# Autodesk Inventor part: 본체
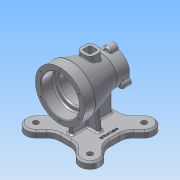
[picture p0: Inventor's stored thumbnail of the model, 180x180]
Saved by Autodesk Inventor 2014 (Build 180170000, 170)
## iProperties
Created: 2018-03
Part Number: 본체
Material: 알루미늄 6061
Document SubType Name: Modeling
Designer: user
Density: 2.71 g/cm^3
Appearance: 알루미늄 - 평지
Mass: 1019.39 g
Surface Area: 857.336 cm^2
Volume: 376.16 cm^3
Author: user
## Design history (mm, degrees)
sketch "스케치1"
  geometry: L1 (0, 0)-(0, 45); L2 (0, 45)-(20, 45); L3 (20, 45)-(77, 27.5); L4 (0, 0)-(100, 0); L5 (77, 27.5)-(100, 27.5); L6 (100, 27.5)-(100, 0)
  constraints: 12 end point, 2 perpendicular, 1 parallel, 1 vertical
  dimensions: "d0" = 20 distance of L1.end L2.end; "d2" = 90 diameter of L2 L4; "d4" = 100 distance between parallel lines of L6 L1; "d5" = 55 diameter of L5.end L4; "d6" = 77 distance from line of L1 L3.end
revolve "회전1" sketch "스케치1" stored, may be unused: angle "d7" = 90 deg
node "작업 평면1"
sketch "스케치2"
  geometry: L1 (55, 0)-(5.503, 49.497); L2 (55, 0)-(-15, 0); L3 (10, -45)-(100, 45); L4 (100, -45)-(10, 45); L5 (64.189, 45)-(45.811, 45); L6 (45.811, -45)-(64.189, -45); L7 (10, 9.189)-(10, -9.189); L8 (100, -9.189)-(100, 9.189); L9 (18.23, 62.225)-(28.134, 52.322); L10 (91.77, 62.225)-(81.866, 52.322); L11 (-7.225, 36.77)-(2.678, 26.866); L12 (2.678, -26.866)-(-7.225, -36.77); L13 (28.134, -52.322)-(18.23, -62.225); L14 (117.225, 36.77)-(107.322, 26.866); L15 (107.322, -26.866)-(117.225, -36.77); L16 (81.866, -52.322)-(91.77, -62.225); C1 r 5 at (5.503, 49.497); C2 r 5 at (5.503, -49.497); C3 r 5 at (104.497, -49.497); C4 r 5 at (104.497, 49.497); A1 r 70 centre (55, 0) between (-15, 0) and (5.503, 49.497); A2 r 18 centre (5.503, 49.497) between (18.23, 62.225) and (-7.225, 36.77); A3 r 18 centre (5.503, -49.497) between (18.23, -62.225) and (-7.225, -36.77); A4 r 18 centre (104.497, -49.497) between (117.225, -36.77) and (91.77, -62.225); A5 r 18 centre (104.497, 49.497) between (91.77, 62.225) and (117.225, 36.77); A6 r 25 centre (45.811, 70) between (28.134, 52.322) and (45.811, 45); A7 r 25 centre (64.189, 70) between (64.189, 45) and (81.866, 52.322); A8 r 25 centre (-15, 9.189) between (10, 9.189) and (2.678, 26.866); A9 r 25 centre (-15, -9.189) between (2.678, -26.866) and (10, -9.189); A10 r 25 centre (45.811, -70) between (45.811, -45) and (28.134, -52.322); A11 r 25 centre (64.189, -70) between (81.866, -52.322) and (64.189, -45); A12 r 25 centre (125, -9.189) between (100, -9.189) and (107.322, -26.866); A13 r 25 centre (125, 9.189) between (107.322, 26.866) and (100, 9.189); 1 further point
  constraints: 32 end point, 28 tangent, 26 point on circle, 17 centre point, 7 equal radius, 5 parallel, 5 perpendicular, 2 coincident, 2 horizontal, 2 midpoint, 1 concentric, 1 horizontal alignment, 18 other
  dimensions: "d9" = 55 distance of L1.start point (0, 0); "d10" = 140 diameter of A1; "d11" = 45 deg angle of L2 L1; "d12" = 10 diameter of C1; "d15" = 360 deg dimension on L1.start C1.centre (derived); "d17" = 36 diameter of A2; "d20" = 360 deg dimension on L1.start A2.centre (derived); "d22" = 90 distance of L4.end L3.end; "d23" = 90 distance of L3.end L4.start; "d24" = 25 radius of A6; "d25" = 90 distance between parallel lines of L6 L5; "d26" = 90 distance between parallel lines of L8 L7; "d27" = 90 deg angle of L4 L14; "d28" = 90 diameter of L5 L2; "d29" = 100 distance from line of point (0, 0) L8; "d30" = 45.63961 distance from line of L3.end L15; "d31" = 81.63961 distance from line of L3.start L15
extrude "돌출1" join sketch "스케치2" distance "d32" = 12; taper "d33" = 0 deg
sketch "스케치3"
  geometry: L1 (-91.77, 62.225)-(-81.866, 52.322) reference; L2 (-64.189, 45)-(-45.811, 45) reference; L3 (-28.134, 52.322)-(-18.23, 62.225) reference; L4 (7.225, 36.77)-(-2.678, 26.866) reference; L5 (-10, 9.189)-(-10, -9.189) reference; L6 (-2.678, -26.866)-(7.225, -36.77) reference; L7 (-18.23, -62.225)-(-28.134, -52.322) reference; L8 (-45.811, -45)-(-64.189, -45) reference; L9 (-81.866, -52.322)-(-91.77, -62.225) reference; L10 (-117.225, -36.77)-(-107.322, -26.866) reference; L11 (-100, -9.189)-(-100, 9.189) reference; L12 (-107.322, 26.866)-(-117.225, 36.77) reference; L13 (-92, 4)-(-18, 4); L14 (-18, 4)-(-18, -4); L15 (-18, -4)-(-92, -4); L16 (-92, -4)-(-92, 4); L17 (-92, 4)-(-18, -4); L18 (-18, 4)-(-92, -4); C1 r 5 at (-5.503, -49.497) reference; C2 r 5 at (-104.497, 49.497) reference; C3 r 5 at (-104.497, -49.497) reference; C4 r 5 at (-5.503, 49.497) reference; A1 r 25 centre (-64.189, 70) between (-81.866, 52.322) and (-64.189, 45) reference; A2 r 25 centre (-45.811, 70) between (-45.811, 45) and (-28.134, 52.322) reference; A3 r 18 centre (-5.503, 49.497) between (7.225, 36.77) and (-18.23, 62.225) reference; A4 r 25 centre (15, 9.189) between (-2.678, 26.866) and (-10, 9.189) reference; A5 r 25 centre (15, -9.189) between (-10, -9.189) and (-2.678, -26.866) reference; A6 r 18 centre (-5.503, -49.497) between (-18.23, -62.225) and (7.225, -36.77) reference; A7 r 25 centre (-45.811, -70) between (-28.134, -52.322) and (-45.811, -45) reference; A8 r 25 centre (-64.189, -70) between (-64.189, -45) and (-81.866, -52.322) reference; A9 r 18 centre (-104.497, -49.497) between (-117.225, -36.77) and (-91.77, -62.225) reference; A10 r 25 centre (-125, -9.189) between (-107.322, -26.866) and (-100, -9.189) reference; A11 r 25 centre (-125, 9.189) between (-100, 9.189) and (-107.322, 26.866) reference; A12 r 18 centre (-104.497, 49.497) between (-91.77, 62.225) and (-117.225, 36.77) reference; 5 further points
  constraints: 12 end point, 5 midpoint, 2 parallel, 1 horizontal, 1 horizontal alignment, 1 perpendicular, 1 vertical alignment
  dimensions: "d34" = 37 distance from line of L14 point (-55, 0); "d35" = 8 distance of L13.end L14.end
extrude "돌출2" join sketch "스케치3" stored distance "d36" = 12; taper "d37" = 0 deg
node "작업 평면2"
sketch "스케치6"
  geometry: L1 (-70, -66.927)-(-82, -66.927) reference; L2 (-82, -66.927)-(-82, -51.682) reference; L3 (-70, -51.682)-(-70, -66.927) reference; L4 (-82, 66.927)-(-70, 66.927) reference; L5 (-70, 66.927)-(-70, 51.682) reference; L6 (-82, 51.682)-(-82, 66.927) reference; L7 (-70, 9.189)-(-82, 9.189) reference; L8 (-82, -9.189)-(-82, 9.189) reference; L9 (-82, -47.313)-(-82, -9.189) reference; L10 (-70, -47.313)-(-82, -47.313) reference; L11 (-70, -9.189)-(-70, -47.313) reference; L12 (-70, -9.189)-(-82, -9.189) reference; L13 (-70, 9.189)-(-70, -9.189) reference; L14 (-70, 47.313)-(-70, 9.189) reference; L15 (-82, 47.313)-(-70, 47.313) reference; L16 (-82, 9.189)-(-82, 47.313) reference; L17 (-82, -51.682)-(-70, -51.682) reference; L18 (-70, 51.682)-(-82, 51.682) reference; C1 r 7 at (27.5, 0); C2 r 7 at (-13.75, 23.816); C3 r 7 at (-13.75, -23.816); 2 further points
  constraints: 3 centre point, 3 horizontal alignment, 9 other
  dimensions: "d43" = 14 diameter of C1; "d46" = 360 deg dimension on point (0, 0) C1.centre (derived)
extrude "돌출4" join sketch "스케치6" distance "d48" = 15; taper "d49" = 0 deg
sketch "스케치7"
  geometry: C1 r 27.5 at (-27.5, 0); A1 r 7 centre (0, 0) between (-0.891, -6.943) and (-0.891, 6.943) reference; A2 r 7 centre (-41.25, 23.816) between (-34.792, 26.516) and (-46.817, 19.573) reference; A3 r 27.5 centre (-27.5, 0) between (-46.817, 19.573) and (-46.817, -19.573) reference; A4 r 7 centre (-41.25, -23.816) between (-46.817, -19.573) and (-34.792, -26.516) reference; 3 further points
  constraints: 4 coincident, 1 centre point
  dimensions: "d50" = 55 diameter of C1
hole "구멍1" sketch "스케치7" at (0, 0), (-41.25, 23.816), (-41.25, -23.816) diameter "d51" = 3.242; stored, may be unused: countersink angle "d55" = 90 deg, drill point angle "d57" = 118 deg; dims "d52" = 9, "d53" = 4, "d54" = 2, "d56" = 11
sketch "스케치8"
  geometry: C1 r 45 at (0, 0) reference; 7 further points
  constraints: 1 coincident, 1 horizontal alignment, 7 other
  dimensions: "d58" = 40 distance of C1.centre point (-40, 0); "d61" = 360 deg dimension on C1.centre point (-40, 0) (derived)
hole "구멍2" sketch "스케치8" at (-40, 0), (-20, -34.641), (20, -34.641), (40, 0), (20, 34.641), (-20, 34.641) diameter "d63" = 3.242; stored, may be unused: countersink angle "d67" = 90 deg, drill point angle "d69" = 118 deg; dims "d64" = 9, "d65" = 4, "d66" = 2, "d68" = 11
sketch "스케치9"
  geometry: L1 (-100, 70)-(-100, 82) reference; L2 (-100, 82)-(-10, 82) reference; L3 (-10, 82)-(-10, 70) reference; L4 (-10, 70)-(-18, 70) reference; L5 (-18, 70)-(-18, 45) reference; L6 (-18, 45)-(0, 45) reference; L7 (0, 45)-(0, 41.621) reference; L8 (0, 41.621)-(-11, 41.621) reference; L9 (-11, 41.621)-(-11.974, 40) reference; L10 (-11.974, 40)-(-11, 38.379) reference; L11 (-11, 38.379)-(0, 38.379) reference; L12 (0, 38.379)-(0, -38.379) reference; L13 (0, -38.379)-(-11, -38.379) reference; L14 (-11, -38.379)-(-11.974, -40) reference; L15 (-11.974, -40)-(-11, -41.621) reference; L16 (-11, -41.621)-(0, -41.621) reference; L17 (0, -41.621)-(0, -45) reference; L18 (0, -45)-(-20, -45) reference; L19 (-20, -45)-(-77, -27.5) reference; L20 (-77, -27.5)-(-85, -27.5) reference; L21 (-85, -27.5)-(-85, -34.5) reference; L22 (-85, -34.5)-(-100, -34.5) reference; L23 (-100, -34.5)-(-100, -29.121) reference; L24 (-100, -29.121)-(-89, -29.121) reference; L25 (-89, -29.121)-(-88.026, -27.5) reference; L26 (-88.026, -27.5)-(-89, -25.879) reference; L27 (-89, -25.879)-(-100, -25.879) reference; L28 (-100, -25.879)-(-100, 27.5) reference; L29 (-100, 27.5)-(-92, 27.5) reference; L30 (-92, 27.5)-(-92, 70) reference; L31 (-92, 70)-(-100, 70) reference; L32 (0, 0)-(0, -35); L33 (0, -35)-(-20, -35); L34 (-23, -32)-(-23, -29); L35 (-26, -26)-(-67, -26); L36 (-70, -23)-(-70, -23); L37 (-73, -20)-(-100, -20); L38 (-100, -20)-(-100, 0); L39 (-100, 0)-(0, 0); A1 r 3 centre (-20, -32) between (-23, -32) and (-20, -35); A2 r 3 centre (-26, -29) between (-23, -29) and (-26, -26); A3 r 3 centre (-67, -23) between (-70, -23) and (-67, -26); A4 r 3 centre (-73, -23) between (-70, -23) and (-73, -20); 2 further points
  constraints: 16 end point, 8 point on circle, 8 tangent, 4 centre point, 3 equal radius, 3 parallel, 3 perpendicular, 2 midpoint, 2 point on line, 1 collinear, 1 horizontal alignment
  dimensions: "d70" = 70 diameter of L33 L39; "d71" = 52 diameter of L35 L39; "d72" = 40 diameter of L37 L39; "d73" = 23 distance between parallel lines of L32 L34; "d74" = 47 distance between parallel lines of L36 L34; "d75" = 3 radius of A1
revolve "회전2" sketch "스케치9" stored, may be unused: angle "d76" = 90 deg
chamfer "모따기1" distance "d77" = 1; stored, may be unused: second distance "d78" = 2, angle "d79" = 45 deg
node "작업 평면3"
sketch "스케치10"
  geometry: L1 (67.5, 12.5)-(42.5, 12.5); L2 (42.5, 12.5)-(42.5, -12.5); L3 (42.5, -12.5)-(67.5, -12.5); L4 (67.5, -12.5)-(67.5, 12.5); L5 (67.5, 12.5)-(42.5, -12.5); L6 (42.5, 12.5)-(67.5, -12.5); L7 (64.189, -45)-(45.811, -45) reference; L8 (47.5, 7.5)-(62.5, 7.5); L9 (62.5, 7.5)-(62.5, -7.5); L10 (62.5, -7.5)-(47.5, -7.5); L11 (47.5, -7.5)-(47.5, 7.5); L12 (47.5, 7.5)-(62.5, -7.5); L13 (62.5, 7.5)-(47.5, -7.5); 5 further points
  constraints: 24 end point, 7 midpoint, 4 parallel, 2 horizontal, 2 perpendicular, 1 horizontal alignment, 1 vertical alignment
  dimensions: "d81" = 25 distance of L3.end L2.end; "d82" = 25 distance of L2.end L1.end; "d83" = 15 distance of L9.end L10.end; "d84" = 15 distance of L8.end L9.end
extrude "돌출5" join sketch "스케치10" stored distance "d85" = 15; taper "d86" = 0 deg
extrude "돌출6" cut sketch "스케치10" distance "d87" = 30; taper "d88" = 0 deg
fillet "모깎기1" dims "d89" = 8
fillet "모깎기2" dims "d90" = 3
fillet "모깎기3" dims "d91" = 3
fillet "모깎기4" dims "d92" = 1
fillet "모깎기5" dims "d93" = 3
fillet "모깎기6" dims "d94" = 1
fillet "모깎기7" dims "d95" = 3
fillet "모깎기8" dims "d96" = 1
fillet "모깎기9" dims "d97" = 1
chamfer "모따기2" distance "d98" = 3; stored, may be unused: second distance "d99" = 2, angle "d100" = 45 deg
fillet "모깎기10" dims "d101" = 3
sketch "스케치11"
  geometry: L1 (-64.189, 42)-(-45.811, 42) reference; 3 further points
  constraints: 1 midpoint, 1 vertical alignment, 1 other
  dimensions: "d105" = 35 vertical distance of point (-55, 35) point (0, 0)
feature "엠보싱1" sketch "스케치11" dims "d20" = 360 deg (derived), "d106" = 0.5, "d107" = 0
node "작업 평면4"
sketch "스케치12"
  geometry: L1 (-45, -7.458)-(-24.907, -7.458) reference; L2 (-24.907, 7.458)-(-45, 7.458) reference; L3 (-45, 7.458)-(-45, 12.484) reference; L4 (-45, 12.484)-(-34.3, 12.484) reference; L5 (35.565, 4)-(70, 4) reference; L6 (70, 4)-(70, 35.982) reference; L7 (70, 35.982)-(69.5, 35.982) reference; L8 (69.5, 35.982)-(69.5, 36.994) reference; L9 (69.5, 36.994)-(70, 36.994) reference; L10 (70, 36.994)-(70, 42) reference; L11 (70, 42)-(73, 45) reference; L12 (73, 45)-(82, 45) reference; L13 (82, 45)-(82, -45) reference; L14 (82, -45)-(73, -45) reference; L15 (73, -45)-(70, -42) reference; L16 (70, -42)-(70, -4) reference; L17 (70, -4)-(35.565, -4) reference; L18 (-34.3, -12.484)-(-45, -12.484) reference; L19 (-45, -12.484)-(-45, -7.458) reference; L20 (70, 24)-(70, -24); L21 (70, -24)-(27.739, -20.303); L22 (27.739, 20.303)-(70, 24); L23 (27.739, -20.303)-(27.739, 20.303); A1 r 26 centre (0, 0) between (-24.907, -7.458) and (-24.907, 7.458) reference; A2 r 35.789 centre (0, 0) between (35.565, 4) and (-33.287, 13.146) reference; A3 r 35.789 centre (0, 0) between (-33.287, -13.146) and (35.565, -4) reference; 3 further points
  constraints: 8 end point, 2 midpoint, 2 parallel, 1 collinear, 1 equal length, 1 horizontal alignment, 2 other
  dimensions: "d109" = 95 deg angle of L10 L22; "d110" = 24 distance of point (70, 0) L20.start
extrude "돌출7" join sketch "스케치12" stored distance "d111" = 8; taper "d112" = 0 deg
fillet "모깎기14" dims "d113" = 3
fillet "모깎기15" dims "d114" = 3
fillet "모깎기16" dims "d115" = 3
fillet "모깎기17" dims "d116" = 3
node "솔리드1"
node "절단 모서리 투영1"
node "절단 모서리 투영3"
node "절단 모서리 투영4"
node "절단 모서리 투영5"
other parameters: "d8" = 82, "d80" = -45
